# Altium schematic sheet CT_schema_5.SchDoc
size 218 x 258 mm
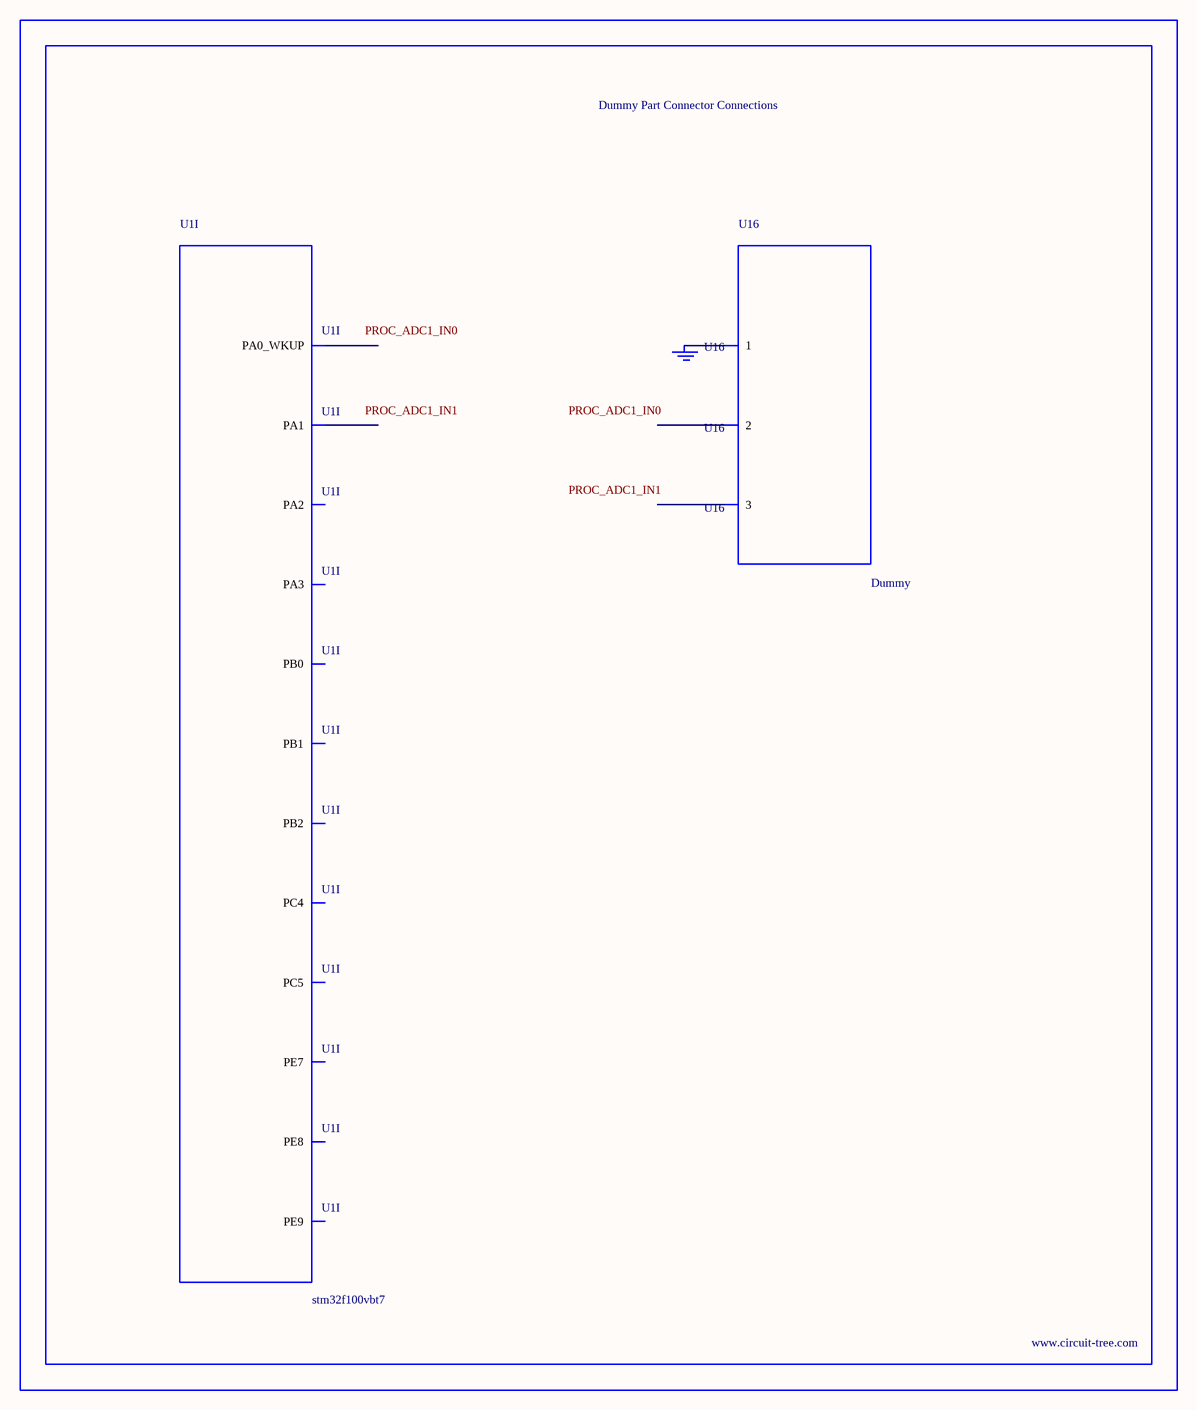
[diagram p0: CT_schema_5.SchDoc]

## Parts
BORDER4  (no value)
GND_INSTANCE_4_0  (no value)
U1  stm32f100vbt7  [LQFP100]  (part I of 9)
U16  Dummy  [DUMMY_PACKAGE_140]

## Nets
NetGND_INSTANCE_4_0_0: GND_INSTANCE_4_0.0(GND) U16.1

Not connected (* = marked no-connect by the designer): U1 23(PA0_WKUP) 24(PA1) 25(PA2) 26(PA3) 33(PC4) 34(PC5) 35(PB0) 36(PB1) 37(PB2) 38(PE7) 39(PE8) 40(PE9); U16 2 3

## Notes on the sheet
- Labels drawn without touching a wire or pin: PROC_ADC1_IN0, PROC_ADC1_IN1

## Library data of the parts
BORDER4 = BORDER_PAGE4
GND_INSTANCE_4_0 = GND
